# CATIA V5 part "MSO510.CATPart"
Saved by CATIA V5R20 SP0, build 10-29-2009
Part number: MSO510
Definition: NONE
Nomenclature: MSO510
Source: Unknown
Description: MSO510
Bounding box of the stored display mesh (mm): x 0 to 12, y -5 to 5, z -5 to 5
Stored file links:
  C:\Users\Utente\Desktop\IO LAVORO\3D X SITO CF\X SITO\PLASTICA\CFMR\MSO510.CATPart
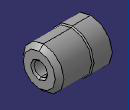
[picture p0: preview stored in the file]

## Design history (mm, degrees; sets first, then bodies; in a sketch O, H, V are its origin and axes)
Body1 "MSO510" (main body)
  Solid1: solid without history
